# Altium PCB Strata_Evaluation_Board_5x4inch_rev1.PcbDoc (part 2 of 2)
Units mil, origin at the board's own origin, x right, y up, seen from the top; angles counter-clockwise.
Board outline 5000 x 4000 mil, 2 copper layers (Top Layer, Bottom Layer); 99 components, 40 nets, 363 pads, 393 vias.
Unrouted connection lines stored in the file: 5.
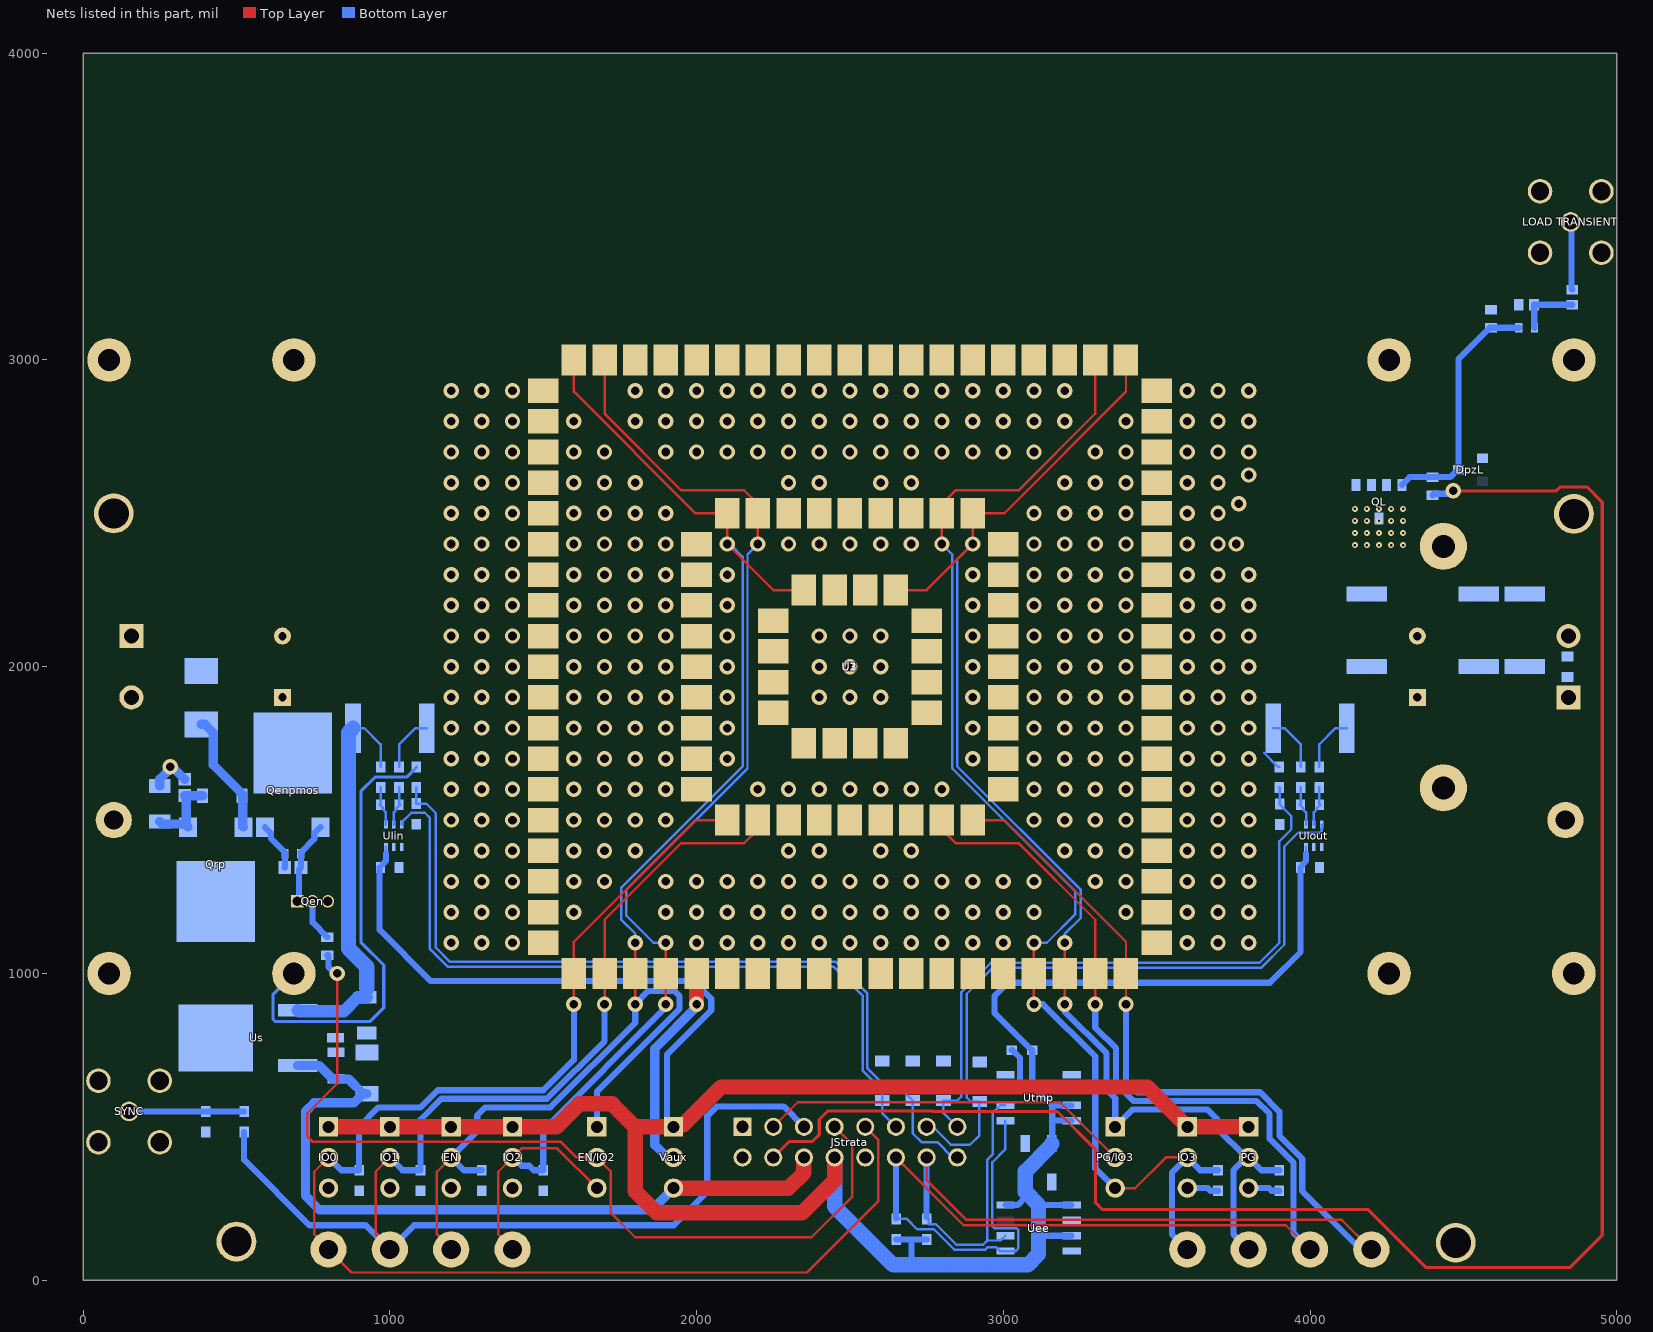
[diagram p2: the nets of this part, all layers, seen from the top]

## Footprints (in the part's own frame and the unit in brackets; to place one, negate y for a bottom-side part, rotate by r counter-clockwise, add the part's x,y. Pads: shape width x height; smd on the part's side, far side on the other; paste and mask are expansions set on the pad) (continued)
SC-88/SC70-6/SOT-363 [mm] "SC-88/SC70-6/SOT-363, CASE 419B-02, Issue Y"
  rect 0.66x0.3 smd: 1(-0.92,0.65) 2(-0.92,0) 3(-0.92,-0.65) 4(0.92,-0.65) 5(0.92,0) 6(0.92,0.65)
  silkscreen extent -1.04,-1.1 0.3,1.48, body extent -1.1,-1.1 1.1,1.1, height 1.1
SMB_STR_TH [mil]
  round 64 hole 48: 1(0,0)
  round 80 hole 59.5: 2(-100,-100) 2(-100,100) 2(100,-100) 2(100,100)
  silkscreen extent -125,-125 125,125, body extent -138,-138 138,138, height 300
SOD-123 [mm] "SOD, 2-Leads, Body 2.69x1.6mm"
  rect 0.91x1.22 smd: 1(-1.635,0) 2(1.635,0)
  silkscreen extent -1.76,-0.8 0.78,1.29, body extent -1.85,-0.8 1.85,0.8, height 1.27
SOIC-8 [mm] "SOIC-8 NB, CASE 751-7, Issue AK"
  rect 1.52x0.6 smd: 1(-2.74,1.905) 2(-2.74,0.635) 3(-2.74,-0.635) 4(-2.74,-1.905) 5(2.74,-1.905) 6(2.74,-0.635) 7(2.74,0.635) 8(2.74,1.905)
  silkscreen extent -2.83,-2.45 1.55,2.88, body extent -3,-2.45 3,2.45, height 1.75
"Terminal Turret" [mm]
  round 3.3 hole 2.5: 1(0,0)
  silkscreen extent -2.03,-2.03 2.03,2.03, body extent -1.59,-1.59 1.59,1.59, height 5.56
TestPoint_1.6mm [mm]
  round 3 hole 1.6: 1(0,0)
  silkscreen extent -1.78,-1.78 1.78,1.78, body extent -1.59,-1.59 1.59,1.59, height 8.13

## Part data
Cen Cgsp: library part CMP-2100-03600-1, "Chip Capacitor, 10 nF, +/- 10%, 50 V, -55 to 125 degC, 0603 (1608 Metric), RoHS, Tape and Reel", Capacitance=10nF, Case/Package=0603, Case Code (Metric)=1608, Dielectric=X7R, Insulation Resistance=100GR, Manufacturer=Yageo, Max Operating Temperature=125degC, Min Operating Temperature=-55degC, MPN=CC0603KRX7R9BB103, Package Description="2-Pin Surface Mount Device, Body 1.6 x 0.8 mm", Package Quantity=1, Tolerance=10%, Voltage=50V
Cfi Cfo: "10nF; 50V; X7R; 10%; 0603; GCJ188R71H103KA01D; Murata", Manufacturer=Murata, Package=0603, Rating=50V, Supplier Part Number 1=490-5762-2-ND, Tolerance=10%, Value/Rating=10n/50V
Cfl Csi Cso: "0.1uF; 50V; X7R; 10%; 0603; GRM188R70J474KA01D; Murata", Manufacturer=Murata, Package=0603, Rating=50V, Supplier Part Number 1=490-5798-2-ND, Tolerance=10%, Value/Rating=0.1u/50V
Cin: library part 100uF_Rad_63V_ELYT, "100uF; 63 V; 20%; EEUFR1J101B; Panasonic", Manufacturer=Panasonic, MPN=EEUFR1J101B, Package=Rad_5, Rating=63V, Supplier Part Number 1=P15287TB-ND, Tolerance=20%, Value/Rating=100u/63V
Cin1: "10uF; 25V; X7R; 10%; 1206; GRT31CR71E106KE13; Murata", Manufacturer=Murata, MPN=GRM32EE70G107ME19L, Package=1206, Rating=25V, Tolerance=10%, Value/Rating=10u/25V
Cin2 Csmem Cstmp: "1uF; 50V; X7R; 10%; 0805; GCM21BR71H105KA03L; Murata", Manufacturer=Murata, Package=0805, Rating=50V, Supplier Part Number 1=490-10675-1-ND, Tolerance=10%, Value/Rating=1u/50V
CL: library part Current_Loop_2.5sqmm, "Current Loop Wire for Osciloscope Current Probe", Manufacturer=N/A, Package="2.5 sqmm Cu Wire", Rating=1W, Tolerance="Wire Loop", Value/Rating=0.005/1W
Cout: library part 100uF_Rad_63V_ELYT, "100uF; 63 V; 20%; EEUFR1J101B; Panasonic", Manufacturer=Panasonic, MPN=EEU-FR1J101B, Package=Rad_5, Rating=63V, Supplier Part Number 1=P15287TB-ND, Tolerance=20%, Value/Rating=100u/63V
Cout1: "22uF; 10V; X7R; 10%; 1206; GCM31CR71A226KE02L; Murata", Manufacturer=Murata, Package=1206, Rating=10V, Supplier Part Number 1=490-14439-1-ND, Tolerance=10%, Value/Rating=22u/10V
Cout2: "4.7uF; 10V; X7R; 10%; 0805; GCM21BR71C475KA73L; Murata", Manufacturer=Murata, Package=0805, Rating=10V, Supplier Part Number 1=490-5332-1-ND, Tolerance=10%, Value/Rating=4.7u/10V
Dii Div Doi Dov: "MMSZ52xxxT1G; 3.0V/0.5W; SOD-123; ON Semiconductor", Manufacturer="ON Semiconductor", Package=SOD-123, Rating=3.0V/0.5W, Supplier Part Number 1=MMSZ5225BT1GOSCT-ND, Tolerance=5%
Dpz: library part CMP-1060-00571-1, "Zener Voltage Regulator, 500 mW, 2-Pin SOD-123, Pb-Free, Tape and Reel", Manufacturer="On Semiconductor", MPN=MMSZ5230BT1G, Package=SOD-123-2-425-04
DpzL: library part CMP-1060-00917-1, "Zener Voltage Regulator, 225 mW, 3-Pin SOT-23, Pb-Free, Tape and Reel", Manufacturer="On Semiconductor", MPN=SZBZX84C6V2LT1G, Package=SOT-23-3-318-08
Dz: library part CMP-1060-00144-1, "36V, 3 W Zener Voltage Regulator, 2-Pin SMB, Pb-Free, Tape and Reel", Manufacturer="On Semiconductor", MPN=1SMB5938BT3G, Package=SMB-2-403A-03_H
EN EN/IO2 IO0 IO1 IO2 IO3 PG PG/IO3 Vaux: library part Header3_EB_IO, "Board-To-Board Connector; Header; 36;  22-28-4360", Manufacturer="Würth electronics", MPN=61300311121, Supplier Part Number 1=732-5316-ND, Value/Rating="3 POS"
GND_in GND_out: library part Banana_Socket_10A_Black, "10A; 4mm; TH; Black; 571-0100-01 ; DELTRON", Manufacturer=DELTRON, Value/Rating=Black
J4 J5 J6 J7: library part TestPoint_2.37mm, "TestPoint; 2.37mm; TH; CAMBION  160-1026-02-01-00  TERMINAL", Manufacturer=CAMBION
J8 J9 J10 J11 J12 J13 J14 J15 J16 J17: library part TestPoint_1.6mm, "TestPoint; 1.6mm; TH; Keystone 5010", Manufacturer=KEYSTONE, Supplier Part Number 1=36-5010-ND
Jin Jout: library part Screw_Terminal_Large, "Large Screw Terminal,  TERM BLK 2P SIDE ENT 5.08MM PCB", Manufacturer=Samtec, MPN=TSW-102-07-G-S, Supplier Part Number 1=SAM1029-02-ND
JStrata: library part 613016243121_STRATA, "THT Angled Socket Header WR-PHD, Pitch 2.54 mm, Dual Row, 16 pins", Contact Resistance="20 mOhm", Manufacturer="WUERTH ELECTRONIC", Operating Temperature="-40 to 125 degC", Rated Current="3 A", Withstanding Voltage="500 VAC", Working Voltage="250 VAC"
"LOAD TRANSIENT" SYNC: "SMB JACK STR; 50 OHM; TH; 1-1337482-0", Manufacturer="TE Connectivity", MPN=1-1337482-0, Package=SMB, Supplier Part Number 1=A102025-ND
Qen: library part CMP-1048-01466-1, "Amplifier Transistor, NPN Silicon, 3-Pin TO-92, Bulk Box", Manufacturer="On Semiconductor", PartNumber=BC546B, Supplier Part Number 1=BC546BTFCT-ND
Qenpmos Qrp: library part CMP-1058-00013-1, "P-Channel Power MOSFET, -40 V, -70 A, 10.4 mOhm, Single, 3-Pin ATPAK, Pb-Free, Tape and Reel", Manufacturer="On Semiconductor", Package="DPAK (Single Gauge) / ATPAK", Supplier Part Number 1=ATP108-TL-HOSCT-ND
QL: library part CMP-1058-00242-1, "Single N-Channel Logic Level Power MOSFET, 30 V, 230 A, 1.15 mO", Manufacturer="On Semiconductor", Package=DFN-5-488AA, Package Type="SO-8FL / DFN-5"
RdG: library part CMP-2100-03662-1, "Chip Resistor, 100 KOhm, +/- 1%, 0.1 W, -55 to 155 degC, 0603 (1608 Metric), RoHS, Tape and Reel", Case/Package=0603, Case Code (Metric)=1608, Manufacturer=Yageo, Max Operating Temperature=155degC, Min Operating Temperature=-55degC, MPN=RC0603FR-07100KL, Package Description="2-Pin Surface Mount Device, Body 1.6 x 0.8 mm", Power Rating=100mW, Resistance=100KOhm, Temperature Coefficient=100ppm/degreesC, Tolerance=1%, Voltage Rating=50V
Ren1: library part CMP-2000-06942-1, "Chip Resistor, 4.7 KOhm, +/- 1%, 0.1 W, -55 to 155 degC, 0603 (1608 Metric), RoHS, Tape and Reel", Case Code - in=0603, Case Code - mm=1608, Manufacturer=Yageo, MPN=RC0603FR-074K7L, Operating Temperature Range=-55Cto+155C, Package Description="2-Pin Surface Mount Device, Body 1.6 x 0.8 mm", Power Rating=100mW, Resistance=4.7kOhms, Temperature Coefficient=100PPM/C, Tolerance=1%, Voltage Rating=50V
Ren2: library part CMP-2100-03664-1, "Chip Resistor, 10 KOhm, +/- 1%, 01 W, -55 to 155 degC, 0603 (1608 Metric), RoHS, Tape and Reel", Case/Package=0603, Case Code (Metric)=1608, Manufacturer=Yageo, Max Operating Temperature=155degC, Min Operating Temperature=-55degC, MPN=RC0603FR-0710KL, Package Description="2-Pin Surface Mount Device, Body 1.6 x 0.8 mm", Power Rating=100mW, Resistance=10KOhm, Temperature Coefficient=100ppm/degreesC, Tolerance=1%, Voltage Rating=75V, Voltage Rating (DC)=50V
ReuG: library part CMP-2000-06952-1, "Chip Resistor, 1.2 KOhm, +/- 5%, 0.1 W, -55 to 155 degC, 0603 (1608 Metric), RoHS, Tape and Reel", Case Code - in=0603, Case Code - mm=1608, Manufacturer=Yageo, MPN=RC0603JR-071K2L, Operating Temperature Range=-55Cto+155C, Package Description="2-Pin Surface Mount Device, Body 1.6 x 0.8 mm", Power Rating=100mW, Resistance=1.2kOhms, Temperature Coefficient=100PPM/C, Tolerance=5%, Voltage Rating=50V
Rgsp: library part CMP-13261-000768-1, "RES SMD 10K OHM 1% 1/4W 1206", Case Code (Imperial)=1206, Case Code (Metric)=3216, Manufacturer="Samsung Electro-Mechanics", Max Operating Temperature=155°C, Max Power Dissipation=250mW, Min Operating Temperature=-55°C, MPN=RC3216F103CS, Resistance=10kR, Temperature Coefficient=100ppm/°C, Tolerance=1%, Voltage Rating (DC)=200V
Ril Rol: library part 1k_0603_0.01%, "1k; 1/10W; 0.5%; 0603;  Vishay", Manufacturer=Vishay, Package=0603, Rating=1/10W, Supplier Part Number 1=MCT0603-1.0K-MDCT-ND, Tolerance=0.5%, Value/Rating=1k/1/10W
Rim Rip Ron Rop: library part 4.7_0603_1%_1, "4.7; 1/10W; 1%; 0603; Yageo", Manufacturer=Yageo, Package=0603, Rating=1/10W, Supplier Part Number 1=YAG3371TR-ND, Tolerance=1%, Value/Rating=4R7/1/10W
Rin Rout: library part 0.010R_2512_0.5%, "RES SMD 0.01 OHM 2W 2512; Yageo", Manufacturer=Yageo, Package=2512, Rating=1W, Supplier Part Number 1=PE2512DKM7W0R01L-ND, Tolerance=0.5%, Value/Rating=0.010R/1W
Riu Rou: library part 5.6k_0603_0.01%, "5.62 kOhms ± 0.1% 0.15W chip resistance 0603 (1608 metric) sulfur-free, automotive approval AEC-Q200 thin film", Manufacturer="TE Connectivity Passive Product", Package=0603, Rating=1/10W, Supplier Part Number 1=A139825CT-ND, Tolerance=0.1%, Value/Rating=5.62k/1/10W
Rload1 Rload2 Rload3: library part CMP-1018-00014-1, "3R3 1W 5% 2512 (6432 Metric)  SMD", Case-EIA=2512, Case-Metric=6432, Manufacturer="Vishay Dale", MPN=CRCW25123R30JNEG, Power="1 W", Tolerance="5 %"
Rpd0 Rpd1 Rpd2 Rpd3 RpdEN RpdPG Rscl Rsda Rtmp: library part 10k_0603_1%, "10k; 1/10W; 1%; 0603; Yageo", Manufacturer=Yageo, Package=0603, Rating=1/10W, Supplier Part Number 1=311-10.0KHRCT-ND, Tolerance=1%, Value/Rating=10k/1/10W
Rpdlt1 Rpdlt2: library part CMP-2000-03436-1, "Chip Resistor, 50 Ohm, +/- 1%, 0.1 W, -55 to 155 degC, 0603 (1608 Metric), RoHS, Tape and Reel", Manufacturer="Vishay Dale", MPN=CRCW060350R0FKEA
Rpds: library part 51_0603_1%, "51; 1/10W; 1%; 0603; Yageo", Manufacturer=Yageo, Package=0603, Rating=1/10W, Supplier Part Number 1=311-51.0HRTR-ND, Tolerance=1%, Value/Rating=51/1/10W
Rpus: library part 0R_0603, "RES SMD 0 OHM JUMPER 0603; Yageo", Manufacturer=Yageo, MPN=RC2512JK-070RL, Package=2512, Rating=1W, Supplier Part Number 1=YAG1232CT-ND, Tolerance=Jumper, Value/Rating=0R/1W
RtrG: library part CMP-1659-00018-2, "General Purpose Chip Resistors, 220 Ohm, +/- 1%, -55 to 155 degC, 0603 (1608 Metric), RoHS, Tape and Reel", MPN=RC0603FR-07220RL, Package=0603
U1: "PCB Footprint for 0.5 x 0.5 inch PCB Module"
U2: "PCB Footprint for 1 x 1 inch PCB Module"
U3: "PCB Footprint for 2 x 2 inch PCB Module"
Uee: "EEPROM Serial 512-Kb I2C; SO-8; ON Semiconductor", Manufacturer="ON Semiconductor", MPN="CAT24C512WI GT3", Package=SO-8, Supplier Part Number 1=CAT24C512WI-GT3OSTR-ND, Value/Rating=CAT24C512WI-GT3
UIin UIout: "Current-Shunt Monitors, Voltage Output, Bidirectional Zero-Drift, Low- or High-Side Current Sensing; SO-8; ON Semiconductor", Manufacturer="ON Semiconductor", MPN=NCV213RSQT2G, Package=SC-88/SC70-6/SOT-363, Supplier Part Number 1=NCV213RSQT2GOSTR-ND
Us: library part NCV8664C, "NCV8664C; 5V/150mA, 2.0% Very Low Iq, Low Dropout Linear Regulator; DPAK-3; ON Semiconductor", Manufacturer="ON Semiconductor", MPN=NCV8664CDT50RKG, Package=DPAK-3, Supplier Part Number 1=NCV8664CDT50RKG-ND
Utmp: "Industry Standard Digital Temperature Sensor with / 2-wire Interface; SO-8; ON Semiconductor", Manufacturer="ON Semiconductor", MPN=NCT375DR2G, Package=SO-8, Supplier Part Number 1=NCT375DR2G-ND
Vin Vout: library part Banana_Socket_10A_Red, "10A; 4mm; TH; Red; 571-0500-01 ; DELTRON", Manufacturer=DELTRON, Value/Rating=Red

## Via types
v1: diameter 50, hole 28, Top Layer to Bottom Layer, tented both sides, 367 vias
v2: diameter 19.68, hole 7.87, Top Layer to Bottom Layer, 20 vias
v3: diameter 250, hole 126, Top Layer to Bottom Layer, 4 vias
v4: diameter 50, hole 28, Top Layer to Bottom Layer, 2 vias

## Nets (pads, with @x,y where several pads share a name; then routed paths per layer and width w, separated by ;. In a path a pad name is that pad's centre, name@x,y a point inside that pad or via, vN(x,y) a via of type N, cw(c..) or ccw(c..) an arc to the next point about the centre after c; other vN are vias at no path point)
3V3: Csi.1 Csmem.1 Cso.1 Cstmp.1 EN.1 IO0.1 IO1.1 IO2.1 IO3.1 JStrata.8 PG.1 Rscl.1 Rsda.1 Rtmp.1 Uee.1 Uee.3 Uee.8 UIin.3 UIout.3 Utmp.7 Utmp.8 Vaux.1 | length 10019.5
  Top Layer w50: IO0.1@800,500 IO1.1@1000,500 EN.1@1200,500 IO2.1@1400,500 1543.1,500 1618.1,575 1725,575 1800,500 ; JStrata.8@2450,400 2450,325 2345,220 1870,220 1800,290 1800,500 ; PG.1@3800,500 IO3.1@3600,500 3470,630 2080,630 1956.5,506.5 1931.5,506.5 Vaux.1@1925,500 1800,500
  Bottom Layer w8: 987.41,1390 UIin.3@987.41,1412.78 ; 3986.91,1390 UIout.3@3986.91,1412.78
  Bottom Layer w20: Csi.1@966.54,1345 966.54,1142.05 1133.59,975 1990.38,975 2047.98,917.4 2047.98,880.04 1904.1,736.17 1904.1,520.9 Vaux.1@1925,500 ; Csi.1@975.69,1354.69 987.41,1366.4 987.41,1390 ; Rsda.1@2650.92,132.75 2700.92,132.75 ; 2700.92,40.92 2700.92,50 2700.92,132.75 ; Rscl.1@2750.92,132.75 2700.92,132.75 ; Uee.8@3007.13,245 3046.54,245 3071.69,270.16 3071.69,288.31 ; 3115,145.35 3115.35,145 Uee.3@3222.87,145 ; 3115,245 Uee.1@3222.87,245 ; Cstmp.1@3158.31,445 3159.52,446.21 3159.52,520 ; Utmp.8@3222.87,520 3159.52,520 ; Utmp.7@3222.87,570 3159.52,570 ; Cso.1@3969.49,1345 3969.49,1069.91 3869.24,969.65 3014.65,969.65 2970.86,925.86 2970.86,871.5 3092.35,750 Rtmp.1@3094.32,750 3094.32,635.2 3159.52,570 ; Cso.1@3975.19,1354.69 3986.91,1366.4 3986.91,1390 ; 3159.52,520 3159.52,570
  Bottom Layer w50: JStrata.8@2450,400 2450,240.82 2640.82,50 2700.92,50 3080,50 3115,85 3115,145.35 3115,245 3071.69,288.31 Csmem.1@3071.69,320 3071.69,355.02 3155.75,439.08 3155.75,442.44 Cstmp.1@3158.31,445
5VIN: Cout1.1 Cout2.1 JStrata.6 Us.2 Vaux.3 | length 2493.9
  Top Layer w50: Vaux.3@1925,300 2300,300 2350,350 JStrata.6@2350,400
  Bottom Layer w30: Us.2@700,700 769.88,700 813.19,656.69 Cout2.1@825,656.69 825.75,655.94 865.32,655.94 Cout1.1@913.19,608.07 ; Cout1.1@925,608.07 Cout1.1@913.19,608.07 ; Vaux.3@1925,300 1854.68,229.68 770.32,229.68 725,275 725,550 753.19,578.19 883.31,578.19 Cout1.1@913.19,608.07
5VOUT: JStrata.10
EN: EN.2 EN/IO2.1 J11.1 RpdEN.1 U1.16 U2.36 U3.22 U3.76 | length 4935
  Top Layer w8: J11.1@1200,100 1200,103.45 1153.5,149.95 1153.5,353.5 EN.2@1200,400 ; U3.76@1600,3000 1600,2896.72 1996.72,2500 U2.36@2100,2500 ; v1(1800,900) U3.22@1800,1000 v1(1800,1100) ; U2.36@2100,2510 U2.36@2100,2500 ; U1.16@2350,2250 2250,2250 v1(2100,2400) U2.36@2100,2500
  Bottom Layer w8: RpdEN.1@1300,356.75 RpdEN.1@1300,358.46 ; v1(1800,1100) 1800,1130 1755.17,1174.83 1755.17,1280.17 2150,1675 2150,2358.65 2108.65,2400 v1(2100,2400)
  Bottom Layer w20: RpdEN.1@1300,358.46 1241.54,358.46 EN.2@1200,400 1285,485 1285,537.02 1311.05,563.07 1523.47,563.07 1800,839.6 v1(1800,900) 1843,943 1926.92,943 1944.92,925 1944.92,884.11 1675,614.19 EN/IO2.1@1675,500
EN/IO2: EN/IO2.2 JStrata.7 Ren2.1 | length 2939.6
  Top Layer w8: v4(828.56,1000) 828.56,641.6 731.04,544.08 731.04,468.5 747.61,451.93 1556.75,451.93 1608.68,400 EN/IO2.2@1675,400 1720,355 1720,220 1800,140 2375,140 2508,273 2508,442 JStrata.7@2450,500
  Bottom Layer w20: Ren2.1@795.92,1059.45 799.86,1059.45 799.86,1021.16 817.32,1003.69 v4@819.92,1003.69
G: DpzL.3 QL.4 RdG.1 ReuG.1 RtrG.2 | length 804
  Bottom Layer w20: QL.4@4300,2593.03 4325.2,2618.24 RtrG.2@4399.27,2618.24 4457.24,2618.24 4481.61,2642.6 DpzL.3@4483.57,2642.6 4483.57,3002.71 4586.06,3105.2 RdG.1@4590,3105.2 4590.1,3105.1 4680.69,3105.1 ReuG.1@4680.79,3105
GND: "LOAD TRANSIENT.2" Cfl.2 Cgsp.1 Cin1.2 Cin2.2 Cin.2 Cout1.2 Cout2.2 Cout.2 Csi.2 Csmem.2 Cso.2 Cstmp.2 Dii.2 Div.2 Doi.2 Dov.2 DpzL.1 Dz.2 EN.3 GND_in.1 GND_out.1 IO0.3 IO1.3 IO2.3 IO3.3 J4.1 J5.1 J6.1 J7.1 Jin.1 Jout.2 JStrata.2 PG.3 Qen.3 QL.1 QL.2 QL.3 RdG.2 Rgsp.2 Ril.2 Rol.2 Rpd0.2 Rpd1.2 Rpd2.2 Rpd3.2 RpdEN.2 Rpdlt1.2 RpdPG.2 Rpds.2 SYNC.2 U1.5 U1.6 U1.7 U1.8 U1.14 U1.15 U2.12 U2.13 U2.14 U2.15 U2.16 U2.30 U2.31 U2.32 U2.33 U2.34 U3.25 U3.26 U3.27 U3.28 U3.29 U3.30 U3.31 U3.32 U3.33 U3.34 U3.60 U3.61 U3.62 U3.63 U3.64 U3.65 U3.66 U3.67 U3.68 U3.69 U3.70 U3.71 U3.72 U3.73 U3.74 Uee.2 Uee.4 UIin.1 UIin.2 UIout.1 UIout.2 Us.3 Utmp.4 Utmp.5 Utmp.6 | length 336
  Bottom Layer w20: IO3.3@3600,300 3666.54,300 3675,291.54 Rpd3.2@3700,291.54 ; PG.3@3800,300 3866.54,300 3875,291.54 RpdPG.2@3900,291.54
  Bottom Layer w30: Rgsp.2@250,1611.56 250,1633.44 284.61,1668.05 v1(284.61,1673.46) ; v1@293.92,1670.42 Cgsp.1@331.22,1633.11
  other v1: 2000,1100 2100,1100 2200,1100 2300,1100 2400,1100 2500,1100 2600,1100 2700,1100 2800,1100 2900,1100 3000,1100 1900,1200 2000,1200 2100,1200 2200,1200 2300,1200 2400,1200 2500,1200 2600,1200 2700,1200 2800,1200 2900,1200 3000,1200 3100,1200 1900,1300 2000,1300 2100,1300 2200,1300 2300,1300 2400,1300 2500,1300 2600,1300 2700,1300 2800,1300 2900,1300 3000,1300 3100,1300 2300,1400 2400,1400 2600,1400 2700,1400 2200,1600 2300,1600 2400,1600 2500,1600 2600,1600 2700,1600 2800,1600 2400,1900 2500,1900 2600,1900 2400,2000 2500,2000 2600,2000 2400,2100 2500,2100 2600,2100 2300,2400 2400,2400 2500,2400 2600,2400 2700,2400 2300,2600 2400,2600 2600,2600 2700,2600 1900,2700 2000,2700 2100,2700 2200,2700 2300,2700 2400,2700 2500,2700 2600,2700 2700,2700 2800,2700 2900,2700 3000,2700 3100,2700 1800,2800 1900,2800 2000,2800 2100,2800 2200,2800 2300,2800 2400,2800 2500,2800 2600,2800 2700,2800 2800,2800 2900,2800 3000,2800 3100,2800 3200,2800 1800,2900 1900,2900 2000,2900 2100,2900 2200,2900 2300,2900 2400,2900 2500,2900 2600,2900 2700,2900 2800,2900 2900,2900 3000,2900 3100,2900 3200,2900
Iinm: Dii.1 JStrata.11 UIin.6 | length 2494.3
  Bottom Layer w8: UIin.6@1039.5,1484.31 UIin.6@1038.59,1485.22 1038.59,1492.31 1070.03,1523.75 1107.13,1523.75 1107.33,1523.95 1113.96,1523.95 1129.59,1508.32 1129.59,1081.23 1189.24,1021.58 2447.74,1021.58 2541.19,928.14 2541.19,683.75 2605,619.93 Dii.1@2605,585.63 2605,545 JStrata.11@2650,500
INT: JStrata.4 RtrG.1 | length 6126.1
  Top Layer w10: JStrata.4@2250,400 2301.93,451.93 2377.59,451.93 2400,474.35 2400,523.93 2426.93,550.86 2769.14,550.86 2770,550 3176.64,550 3300,426.64 3300,253.54 3323.54,230 4190,230 4379.06,40.94 4846.89,40.94 4952.75,146.81 4952.75,2536.62 4902.78,2586.6 4816.4,2586.6 4803.15,2573.35 v4(4466.62,2573.35)
  Bottom Layer w20: RtrG.1@4399.27,2559.18 4403.9,2563.8 4448.96,2563.8 4458.5,2573.35 v4(4466.62,2573.35)
IO0-VSEL/DISCH: IO0.2 J10.1 JStrata.9 Rpd0.1 U2.10 U3.20 | length 4617.3
  Top Layer w8: J10.1@800,100 875,25 2360,25 2593,258 2593,457 JStrata.9@2550,500 ; J10.1@800,103.45 753.5,149.95 753.5,353.5 IO0.2@800,400 ; v1(1600,900) U3.20@1600,1000 1600,1103.28 1996.72,1500 U2.10@2100,1500
  Bottom Layer w8: J10.1@800,100 J10.1@800,103.45
  Bottom Layer w20: IO0.2@800,400 841.54,358.46 Rpd0.1@900,358.46 900,500.42 962.65,563.07 1100.39,563.07 1156.71,619.39 1500.59,619.39 1600,718.79 v1(1600,900)
IO1/INT: IO1.2 J12.1 JStrata.5 Rpd1.1 Rpus.1 U2.11 U3.21 | length 4773.4
  Top Layer w8: J12.1@1000,103.45 953.5,149.95 953.5,353.5 IO1.2@1000,400 ; v1(1700,900) U3.21@1700,1000 1700,1175 1950,1425 2155.56,1425 2200,1469.44 U2.11@2200,1500
  Bottom Layer w20: Rpus.1@525,483.07 525,392.11 737.98,179.13 920.87,179.13 J12.1@1000,100 1079.13,179.13 1925.91,179.13 2035,288.22 2035,534.71 2066.8,566.51 2283.49,566.51 JStrata.5@2350,500 ; IO1.2@1000,400 1041.54,358.46 Rpd1.1@1100,358.46 1100,523.08 1168.31,591.39 1512.19,591.39 1700,779.2 v1(1700,900)
IO2: EN/IO2.3 IO2.2 J13.1 Rpd2.1 U2.35 U3.23 U3.75 | length 4186.3
  Top Layer w8: J13.1@1400,103.45 1353.5,149.95 1353.5,353.5 IO2.2@1400,400 1429.53,429.53 1545.47,429.53 EN/IO2.3@1675,300 ; U3.75@1700,3000 1700,2825 1950,2575 2155.56,2575 2200,2530.56 U2.35@2200,2500 v1(2200,2400) ; v1(1900,900) U3.23@1900,1000 v1(1900,1100)
  Bottom Layer w8: J13.1@1400,100 J13.1@1400,103.45 ; IO2.2@1400,400 IO2.2@1403.28,400 ; v1(1900,1100) 1859.17,1100 1771.17,1187.99 1771.17,1273.55 2166,1668.37 2166,2366 v1(2200,2400)
  Bottom Layer w20: IO2.2@1403.28,400 1430.05,373.24 1454.35,373.24 1469.12,358.46 Rpd2.1@1500,358.46 1500,489.23 1900,889.23 v1(1900,900)
IO3: IO3.2 J15.1 PG/IO3.3 Rpd3.1 U2.29 U3.35 U3.59 | length 4158.8
  Top Layer w8: v1(2800,2400) U2.29@2800,2500 2800,2530.56 2844.44,2575 3050,2575 3300,2825 U3.59@3300,3000 ; U2.29@2831.27,2531.27 U2.29@2831.27,2540 ; v1(3100,900) U3.35@3100,1000 v1(3100,1100) ; PG/IO3.3@3364.84,300 3430.16,300 3530.16,400 IO3.2@3600,400
  Bottom Layer w8: v1(2800,2400) 2833.28,2366.72 2833.28,1669.09 3235,1267.37 3235,1193.4 3141.6,1100 v1(3100,1100)
  Bottom Layer w20: v1(3100,900) 3129.27,900 3300,729.28 3300,364.84 PG/IO3.3@3364.84,300 ; J15.1@3600,100 3550,150 3550,350 IO3.2@3600,400 3641.54,358.46 Rpd3.1@3700,358.46
Ioutm: Doi.1 JStrata.13 UIout.6 | length 2291.1
  Bottom Layer w8: JStrata.13@2750,500 2770.98,500 2829.45,441.53 2891.53,441.53 2922.11,472.11 2922.11,580.62 Doi.1@2923.65,582.17 2893.73,582.17 2880.96,594.93 2880.96,933.86 2966.11,1019 3841.64,1019 3916,1093.36 3916,1413.83 3960.82,1458.65 4030.81,1458.65 4038.09,1465.93 UIout.6@4038.09,1485.22
LOAD: CL.1 QL.5 Rload1.1 Rload2.1 Rload3.1
  other v2: 4146.26,2396.48 4185.63,2396.48 4225,2396.48 4264.37,2396.48 4303.74,2396.48 4146.26,2435.85 4185.63,2435.85 4225,2435.85 4264.37,2435.85 4303.74,2435.85 4146.26,2475.22 4185.63,2475.22 4225,2475.22 4264.37,2475.22 4303.74,2475.22 4146.26,2514.59 4185.63,2514.59 4225,2514.59 4264.37,2514.59 4303.74,2514.59
NetCen_1: Cen.1 Qen.1 Qenpmos.1 Ren1.2 | length 273.2
  Bottom Layer w20: Qen.1@697.97,1235 704.31,1241.34 704.31,1338.95 Cen.1@710.65,1345.29 ; Cen.1@710.22,1345.72 710.22,1389.57 Ren1.2@709.78,1390 709.78,1393.94 754.18,1438.33 754.18,1457.17 Qenpmos.1@773.71,1476.7
NetCen_2: Cen.2 Dpz.1 Dz.1 Qenpmos.3 Qrp.3 Ren1.1 | length 558.1
  Bottom Layer w20: Qenpmos.3@592.6,1476.7 612.13,1457.17 612.13,1440.41 658.6,1393.94 Ren1.1@658.6,1390 658.05,1389.45 658.05,1345.84 Cen.2@657.5,1345.29
  Bottom Layer w30: Dz.1@385,1812.24 396.5,1812.24 424,1784.74 424,1680.03 518.74,1585.28 Dpz.1@518.74,1579.18 520.79,1577.13 520.79,1479.17 Qrp.3@522.83,1477.13
NetCfi_1: Cfi.1 Rim.2 UIin.5 | length 131.2
  Bottom Layer w8: UIin.5@1013,1485.22 1013,1525 1022.72,1534.72 1022.72,1539.25 1033.46,1550 1030,1553.46 Rim.2@1030,1606.54
NetCfi_2: Cfi.2 Rip.2 UIin.4 | length 131.4
  Bottom Layer w8: Rip.2@970,1606.54 970,1553.46 966.54,1550 977.28,1539.25 977.28,1535.13 987.41,1525 UIin.4@987.41,1485.22
NetCfo_1: Cfo.1 Ron.2 UIout.5 | length 131.4
  Bottom Layer w8: UIout.5@4012.59,1485.21 4012.59,1524.99 4022.72,1535.11 4022.72,1539.24 4033.46,1549.99 4030,1553.45 Ron.2@4030,1606.54
NetCfo_2: Cfo.2 Rop.2 UIout.4 | length 131.2
  Bottom Layer w8: Rop.2@3970,1606.54 3970,1553.45 3966.54,1549.99 3977.28,1539.24 3977.28,1534.7 3987,1524.99 UIout.4@3987,1485.21
NetCgsp_2: Cgsp.2 Dpz.2 Qrp.1 Rgsp.1 | length 265
  Bottom Layer w30: Rgsp.1@250,1495.37 257.73,1487.63 331.22,1487.63 Qrp.1@341.73,1477.13 336.48,1482.38 336.48,1574.71 Cgsp.2@331.61,1579.57 ; Cgsp.2@331.22,1579.96 Cgsp.2@331.61,1579.57 ; Dpz.2@390,1579.18 389.61,1579.57 Cgsp.2@331.61,1579.57
"NetLOAD TRANSIENT_1": "LOAD TRANSIENT.1" Rpdlt2.2 | length 222.9
  Bottom Layer w20: 4850,3450 4852.5,3447.5 4852.5,3231.71 Rpdlt2.2@4855,3229.21
NetQen_2: Qen.2 Ren2.2 | length 136.4
  Bottom Layer w20: Qen.2@747.97,1235 747.97,1166.46 Ren2.2@795.92,1118.51
NetReuG_2: ReuG.2 Rpdlt1.1 Rpdlt2.1 | length 200.8
  Bottom Layer w20: ReuG.2@4731.97,3105 4730.98,3105.98 4730.98,3179.02 Rpdlt1.1@4730,3180 Rpdlt2.1@4855,3180
NetRtmp_2: Rtmp.2 Utmp.3 | length 173.1
  Bottom Layer w20: Utmp.3@3007.13,620 3025.24,620 3055.05,649.81 3055.05,724.31 3029.36,750 Rtmp.2@3027.39,750
PG: J17.1 PG.2 PG/IO3.1 RpdPG.1 U1.13 U2.28 U3.36 U3.58 | length 4377.1
  Top Layer w8: U1.13@2650,2250 2750,2250 v1(2900,2400) U2.28@2900,2500 ; U2.28@2900,2510 U2.28@2900,2500 ; v1(3200,900) U3.36@3200,1000 v1(3200,1100) ; U3.58@3400,3000 3400,2896.72 3003.28,2500 U2.28@2900,2500
  Bottom Layer w8: v1(2900,2400) 2850,2350 2850,1675 3252.8,1272.2 3252.8,1181.62 3200,1128.83 v1(3200,1100)
  Bottom Layer w20: v1@3213.19,900 v1(3200,900) 3200,875.8 3336.67,739.13 3336.67,621.4 3364.84,593.23 PG/IO3.1@3364.84,500 3421.46,556.62 3665.48,556.62 3695.82,526.29 3695.82,495.72 PG.2@3791.54,400 ; J17.1@3800,100 3750,150 3750,358.46 PG.2@3791.54,400 ; RpdPG.1@3900,358.46 3841.54,358.46 PG.2@3800,400 PG.2@3791.54,400
PG/IO3: JStrata.3 PG/IO3.2 | length 1222.5
  Top Layer w8: JStrata.3@2250,500 2330,580 3184.84,580 PG/IO3.2@3364.84,400
RST: JStrata.1
SCL: J16.1 JStrata.14 Rscl.2 U2.18 U3.38 Uee.6 Utmp.2 | length 4926.4
  Top Layer w8: JStrata.14@2750,400 2750,326.46 2880,196.46 4103.54,196.46 J16.1@4200,100 ; U2.18@2900,1500 2900,1490 2910,1500 3003.28,1500 3400,1103.28 U3.38@3400,1000 ; v1(3400,900) U3.38@3400,1000 ; U3.38@3400,950 U3.38@3400,1000
  Bottom Layer w8: Rscl.2@2750,206.04 Rscl.2@2756.36,199.68 ; Rscl.2@2750.92,199.68 Rscl.2@2756.36,199.68 ; Uee.6@3007.13,145 2991.5,129.37 2948.2,129.37 ; Utmp.2@3007.13,570 2990,570 2965,545 2965,409.84 2948.2,393.05 2948.2,129.37 ; Rscl.2@2756.36,199.68 2756.36,183.64 2757.85,182.15 2780.47,182.15 2846.77,115.86 2934.69,115.86 2948.2,129.37
  Bottom Layer w20: Rscl.2@2750,206.04 JStrata.14@2750,400 ; v1(3400,900) 3400,648.45 3435.83,612.62 3836.98,612.62 3900,549.6 3900,470.07 3974.72,395.34 3974.72,290.28 4165,100 J16.1@4200,100
SDA: J14.1 JStrata.12 Rsda.2 U2.17 U3.37 Uee.5 Utmp.1 | length 4897.8
  Top Layer w8: JStrata.12@2650,400 2870.87,179.13 3920.87,179.13 J14.1@4000,100 ; U2.17@2800,1500 2800,1469.44 2844.44,1425 3050,1425 3300,1175 U3.37@3300,1000 v1(3300,900) ; U2.17@2831.27,1460 U2.17@2831.27,1468.73
  Bottom Layer w8: Rsda.2@2650,200.6 Rsda.2@2650.92,199.68 2685.71,199.68 2719.23,166.15 2773.85,166.15 2840.14,99.86 2941.32,99.86 2948.27,106.81 2977.2,106.81 2989.02,95 Uee.5@3007.13,95 3040,95 3049.05,104.05 3049.05,163.2 3042.24,170 2970.86,170 2964.2,176.65 2964.2,384.2 3007.13,427.13 Utmp.1@3007.13,520
  Bottom Layer w20: Rsda.2@2650,200.6 JStrata.12@2650,400 ; v1(3300,900) 3300,823.35 3367.85,755.5 3367.85,641.01 3424.23,584.62 3825.38,584.62 3867.95,542.05 3867.95,460.83 3946.72,382.05 3946.72,153.28 J14.1@4000,100
SYNC: Rpds.1 Rpus.2 SYNC.1 | length 375
  Bottom Layer w20: SYNC.1@150,550 Rpds.1@400,550 Rpus.2@525,550
Vaux: U3.24 Vaux.2 | length 693.8
  Top Layer w50: v1(2000,900) U3.24@2000,1000
  Bottom Layer w30: Vaux.2@1925,400 1904.68,400 1863.66,441.03 1863.66,754.71 2000,891.06 v1(2000,900)
Vin: Cin1.1 Cin2.1 Cin.1 Qenpmos.4 Rin.1 Rip.1 Us.1 | length 1309.9
  Bottom Layer w8: Rin.1@880,1800 916.54,1800 970,1746.54 Rip.1@970,1673.46
  Bottom Layer w40: Us.1@700,880.31 703.54,876.77 Cin2.1@823.48,876.77 850.08,876.77 895.54,922.23 924.81,922.23 Cin1.1@925,922.05
  Bottom Layer w50: Rin.1@880,1800 865.32,1785.32 865.32,1081.46 925.19,1021.58 925.19,951.55
Vinm: Div.1 JStrata.16 Ril.1 Riu.2 | length 2757
  Bottom Layer w8: Riu.2@1086.41,1606.54 Ril.1@1086.41,1553.46 1118.82,1553.46 1149.8,1522.48 1149.8,1084.05 1196.26,1037.58 2454.37,1037.58 2557.19,934.77 2557.19,690.38 2627.56,620 2670.63,620 Div.1@2705,585.63 2705,478.75 2733.75,450 2785,450 2835,400 JStrata.16@2850,400
Vins: Rim.1 Rin.2 U1.1 U1.2 U1.3 U1.4 U2.1 U2.2 U2.3 U2.4 U2.5 U2.6 U2.7 U2.8 U2.9 U3.1 U3.2 U3.3 U3.4 U3.5 U3.6 U3.7 U3.8 U3.9 U3.10 U3.11 U3.12 U3.13 U3.14 U3.15 U3.16 U3.17 U3.18 U3.19 | length 185.2
  Bottom Layer w8: Rim.1@1030,1673.46 1030,1746.54 1083.46,1800 Rin.2@1120,1800
  other v1: 1200,1100 1300,1100 1400,1100 1200,1200 1300,1200 1400,1200 1600,1200 1200,1300 1300,1300 1400,1300 1600,1300 1700,1300.01 1200,1400 1300,1400 1400,1400 1600,1400 1700,1400 1800,1400 1200,1500 1300,1500 1400,1500 1600,1500 1700,1500 1800,1500 1900,1500 1200,1600 1300,1600 1400,1600 1600,1600 1700,1600 1800,1600 1900,1599.99 1200,1700 1300,1700 1400,1700 1600,1700 1700,1700 1800,1700 1900,1699.99 2100,1700 1200,1800 1300,1800 1400,1800 1600,1800 1700,1800 1800,1800 1900,1799.99 2100,1800 1200,1900 1300,1900 1400,1900 1600,1900 1700,1900 1800,1900 1900,1899.99 2100,1900 1200,2000 1300,2000 1400,2000 1600,2000 1700,2000 1800,2000 1900,1999.99 2100,2000 1200,2100 1300,2100 1400,2100 1600,2100 1700,2100 1800,2100 1900,2099.99 2100,2100 1200,2200 1300,2200 1400,2200 1600,2200 1700,2200 1800,2200 1900,2199.99 2100,2200 1200,2300 1300,2300 1400,2300 1600,2300 1700,2300 1800,2300 1900,2299.99 2100,2300 1200,2400 1300,2400 1400,2400 1600,2400 1700,2400 1800,2400 1900,2399.99 1200,2500 1300,2500 1400,2500 1600,2500 1700,2500 1800,2500 1900,2500 1200,2600 1300,2600 1400,2600 1600,2600 1700,2600 1800,2600 1200,2700 1300,2700 1400,2700 1600,2700 1700,2700 1200,2800 1300,2800 1400,2800 1600,2800 1200,2900 1300,2900 1400,2900
Vout: Cfl.1 CL.2 Cout.1 J9.1 Jout.1 Rload1.2 Rload2.2 Rload3.2 Ron.1 Rout.2 Vout.1 | length 185.2
  Bottom Layer w8: Ron.1@4030,1673.46 4030,1746.52 4083.46,1799.99 Rout.2@4120,1800
Voutm: Dov.1 JStrata.15 Rol.1 Rou.2 | length 2150.1
  Bottom Layer w8: JStrata.15@2850,500 2805,545 Dov.1@2805,585.63 2850,585.63 2862.24,597.87 2862.24,937.75 2959.48,1035 3835.01,1035 3900,1099.99 3900,1430.81 3938.72,1469.54 3938.72,1512.88 3901.43,1550.18 Rol.1@3901.43,1552.15 3901.43,1605.11 Rou.2@3900,1606.54
Vouts: Rop.1 Rou.1 Rout.1 U1.9 U1.10 U1.11 U1.12 U2.19 U2.20 U2.21 U2.22 U2.23 U2.24 U2.25 U2.26 U2.27 U3.39 U3.40 U3.41 U3.42 U3.43 U3.44 U3.45 U3.46 U3.47 U3.48 U3.49 U3.50 U3.51 U3.52 U3.53 U3.54 U3.55 U3.56 U3.57 | length 254.8
  Bottom Layer w8: 3850,1719.99 3850,1719.52 3896.06,1673.45 Rou.1@3900,1673.46 ; Rout.1@3880,1800 3916.54,1799.99 3970,1746.52 Rop.1@3970,1673.46
  other v1: 3600,1100 3700,1100 3800,1100 3400,1200 3600,1200 3700,1200 3800,1200 3300,1300 3400,1300 3600,1300 3700,1299.99 3800,1300 3200,1400.01 3300,1400 3400,1400 3600,1400 3700,1399.99 3800,1400 3100,1500.01 3200,1500 3300,1500 3400,1500 3600,1500 3700,1499.99 3800,1500 3100,1600.01 3200,1600 3300,1600 3400,1600 3600,1600 3700,1599.99 3800,1600 2900,1700 3100,1700.01 3200,1700 3300,1700 3400,1700 3600,1700 3700,1699.99 3800,1700 2900,1800 3100,1800.01 3200,1800 3300,1800 3400,1800 3600,1800 3700,1799.99 3800,1800 2900,1900 3100,1900.01 3200,1900 3300,1900 3400,1900 3600,1900 3700,1899.99 3800,1900 2900,2000 3100,2000.01 3200,2000 3300,2000 3400,2000 3600,2000 3700,1999.99 3800,2000 2900,2100 3100,2100.01 3200,2100 3300,2100 3400,2100 3600,2100 3700,2099.99 3800,2100 2900,2200 3100,2200.01 3200,2200 3300,2200 3400,2200 3600,2200 3700,2199.99 3800,2200 2900,2300 3100,2300.01 3200,2300 3300,2300 3400,2300 3600,2300 3700,2299.99 3800,2300 3100,2400.01 3200,2400 3300,2400 3400,2400 3600,2400 3700,2399.99 3760,2400 3100,2500.01 3200,2500 3300,2500 3400,2500 3600,2500 3700,2499.99 3767.5,2531.39 3200,2600.01 3300,2600 3400,2600 3600,2600 3700,2599.99 3800,2625 3300,2700 3400,2700 3600,2700 3700,2699.99 3800,2700 3400,2800 3600,2800 3700,2800 3800,2800 3600,2900 3700,2900 3800,2900
Vsup: J8.1 Jin.2 Qrp.4 Riu.1 Vin.1 | length 1511.3
  Bottom Layer w10: Vin.1@687.01,1000 619.64,932.62 619.64,849.63 625.49,843.77 936.02,843.77 980.08,887.83 980.08,1027.54 905.59,1102.03 905.59,1593.98 951.62,1640 1054.91,1640 1086.41,1671.5 Riu.1@1086.41,1673.46
pads on no net: DpzL.2 Uee.7
copper on no net:
  other v3: 200,200 4755,230 200,3800 4800,3800

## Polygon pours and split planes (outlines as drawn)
GND on Top Layer "TOP_GND" (solid, remove dead copper, pour order 20): 0,0 5000,0 5000,4000 0,4000
Vouts on Top Layer "TOP_Vin" (solid, remove dead copper, pour order 14): 3491.18,1060.01 2701.18,1850.01 2701.18,2150.01 3491.18,2940.01 3851.18,2940.01 3851.18,1060.01
Vins on Top Layer "TOP_Vin" (solid, remove dead copper, pour order 6): 1510,1060 2300,1850 2300,2150 1510,2940 1150,2940 1150,1060
GND on Bottom Layer "BOT_GND" (solid, remove dead copper, pour order 38): 0,0 5000,0 5000,4000 0,4000 0,2010 325,2010 325,1940 900,1940 900,900 0,900
Vouts on Bottom Layer "VOUTS_L02_P030" (solid, remove dead copper, pour order 30): 3476.18,2924.99 2701.18,2149.99 2701.18,1849.99 3476.18,1074.99 3826.18,1074.99 3826.18,1644.99 3901.18,1719.99 3901.18,1879.99 3826.18,1954.99 3826.18,2924.99
Vins on Bottom Layer "VINS_L02_P026" (solid, remove dead copper, pour order 26): 1525,2925 2300,2150 2300,1850 1525,1075 1175,1075 1175,1645 1100,1720 1100,1880 1175,1955 1175,2925
Vin on Bottom Layer "VIN_L02_P042" (solid, pour order 42): 555.2,1930 887.6,1930 887.6,1539.25 555.2,1539.25
NetCen_2 on Bottom Layer "NETCEN_2_L02_P040" (solid, pour order 40): 480,1520 636.83,1520 636.83,1428.7 480,1428.7
Vout on Bottom Layer "BOT_LOAD" (solid, pour order 36): 4280,2015 4280,1930 4100,1930 4100,2015
LOAD on Bottom Layer "BOT_LOAD" (solid, pour order 34): 4115,2234.58 4115,2536.74 4770,2536.74 4770,2234.58
Vout on Bottom Layer "VOUT_L02_P032" (solid, pour order 32): 5001.18,1995 4100,1995 4100,1721.18 4151.18,1670 4151.18,800 5001.18,800
Vsup on Bottom Layer "VSUP_L02_P028" (solid, pour order 28): 0,1942.92 192.99,1942.92 192.99,1412.78 555.2,1405.75 748.85,1034.6 752.44,972.78 699.94,930.32 0,928.04

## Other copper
Bottom Layer:
  text ".Project_DocumentNumber" at 3100,3850 h60

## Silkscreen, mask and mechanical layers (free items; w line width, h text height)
Top Overlay:
  drawing of 1172 lines, arcs and shapes, not listed
  text "Semiconductor" at 2354,3882 h40
  text "Strata LV DC-DC Ecosystem" at 815,3525 h100
  text "GND" at 2445,3080 h40
  text "EN" at 1615.86,3065 h40 r90
  text "IO2" at 1715.86,3065 h40 r90
  text "IO3" at 3315.86,3065 h40 r90
  text "PG" at 3415.86,3065 h40 r90
  text "GND" at 2445,2585 h40
  text "EN" at 2115.86,2565 h40 r90
  text "IO2" at 2215.86,2565 h40 r90
  text "IO3" at 2815.86,2565 h40 r90
  text "PG" at 2915.86,2565 h40 r90
  text "GND" at 2445,2334.14 h40
  text "EN" at 2365.86,2315 h40 r90
  text "PG" at 2665.86,2315 h40 r90
  text "GND" at 50,2300 h40
  text "GND" at 4800,2300 h40
  text "Vin" at 1370,1950 h40 r90
  text "Vin" at 1867.85,1950 h40 r90
  text "Vin" at 2170,1950 h40 r90
  text "Vout" at 2860,1930 h40 r90
  text "Vout" at 3660,1927.56 h40 r90
  text "Vout" at 3167.85,1925 h40 r90
  text "Vin" at 50,1650 h40
  text "Vout" at 4800,1650 h40
  text "GND" at 2445,1628.37 h40
  text "GND" at 2445,1380 h40
  text "1.8V to 18V DC / 40V Peak Max !!!" at 295,1345 h60
  text "IO0" at 2125,1330 h40 r90
  text "IO1" at 2225,1330 h40 r90
  text "SDA" at 2820,1330 h40 r90
  text "SCL" at 2920,1330 h40 r90
  text "GND" at 2445,880 h40
  text "IO0" at 1625,755 h40 r90
  text "IO1" at 1725,755 h40 r90
  text "EN" at 1825,755 h40 r90
  text "IO2" at 1925,755 h40 r90
  text "IO3" at 3125,755 h40 r90
  text "PG" at 3225,755 h40 r90
  text "SDA" at 3320,755 h40 r90
  text "SCL" at 3420,755 h40 r90
  text "Vaux" at 2025,700 h40 r90
  text "Wireless Strata Linked RSL10" at 2115,557.76 h50
  text "No jumpers for IO0, IO1, EN, IO2 headers / when Strata MCU board is plugged in!" at 365,525 h40
  text "No jumpers for IO3, PG headers / when Strata MCU board is plugged in!" at 2965,525 h40
  text "H" at 720,490 h30
  text "H" at 920,490 h30
  text "H" at 1120,490 h30
  text "H" at 1320,490 h30
  text "EN" at 1565,490 h30
  text "H" at 3520,490 h30
  text "H" at 3720,490 h30
  text "PG" at 3238.32,488.32 h30
  text "3V3" at 1785,480 h30
  text "RoHS Compliant" at 4600,450 h30
  text "L" at 720,290 h30
  text "L" at 920,290 h30
  text "L" at 1120,290 h30
  text "L" at 1320,290 h30
  text "L" at 3520,290 h30
  text "L" at 3720,290 h30
  text "IO2" at 1540,280 h30
  text "5V" at 1815,280 h30
  text "IO3" at 3216.64,278.07 h30
  text "GND" at 4425,230 h40
  text "GND" at 450,225 h40
  text "SDA" at 3950,190 h40
  text "SCL" at 4150,190 h40
  text "Rev. 1" at 4775,8.16 h40
Mechanical 1:
  lines w8: 0,0 0,4000 5000,4000 5000,0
